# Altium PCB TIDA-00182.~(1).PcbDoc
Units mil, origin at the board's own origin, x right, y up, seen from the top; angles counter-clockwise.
Board outline 4330.71 x 3543.31 mil, 2 copper layers (Top Layer, Bottom Layer), stack 62 mil thick; 101 components, 43 nets, 202 pads, 57 vias.
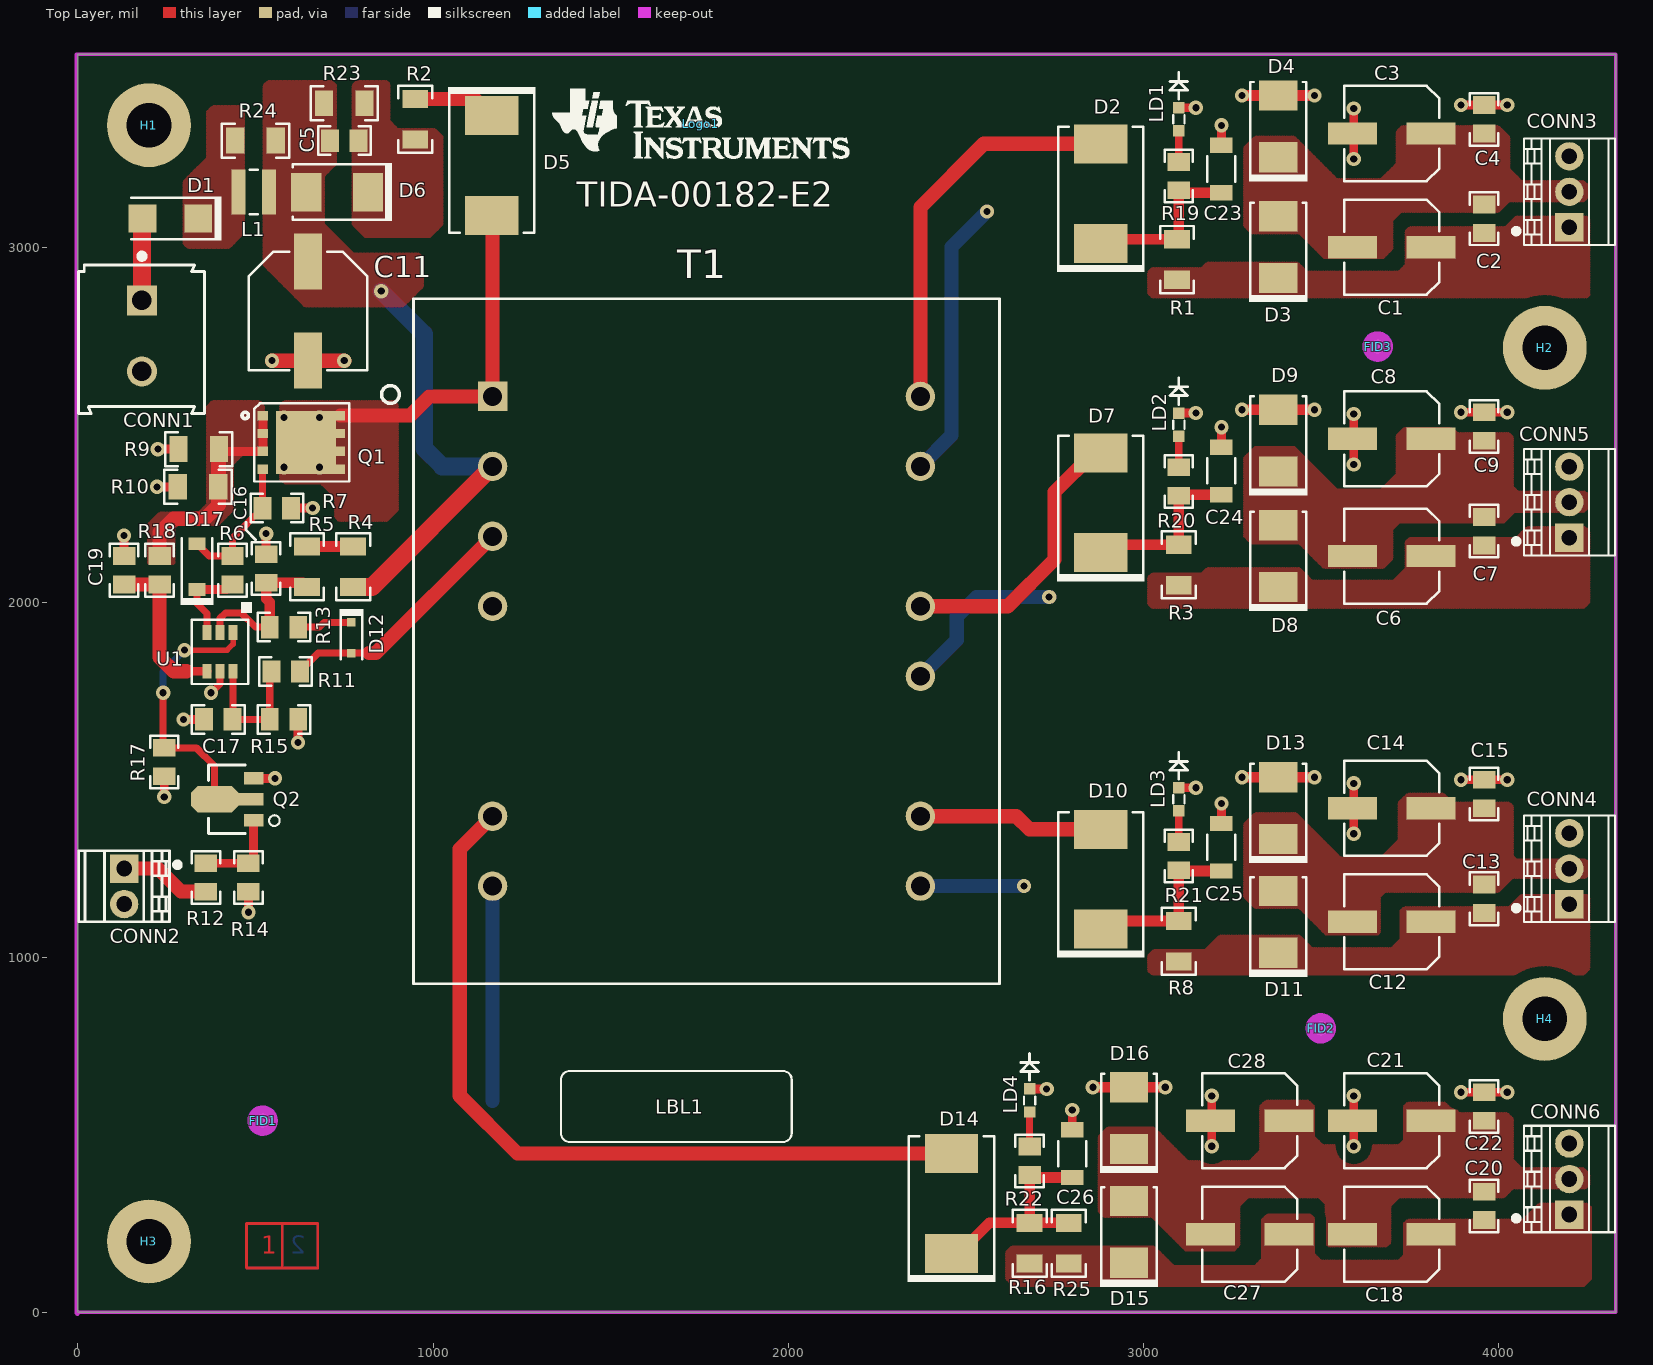
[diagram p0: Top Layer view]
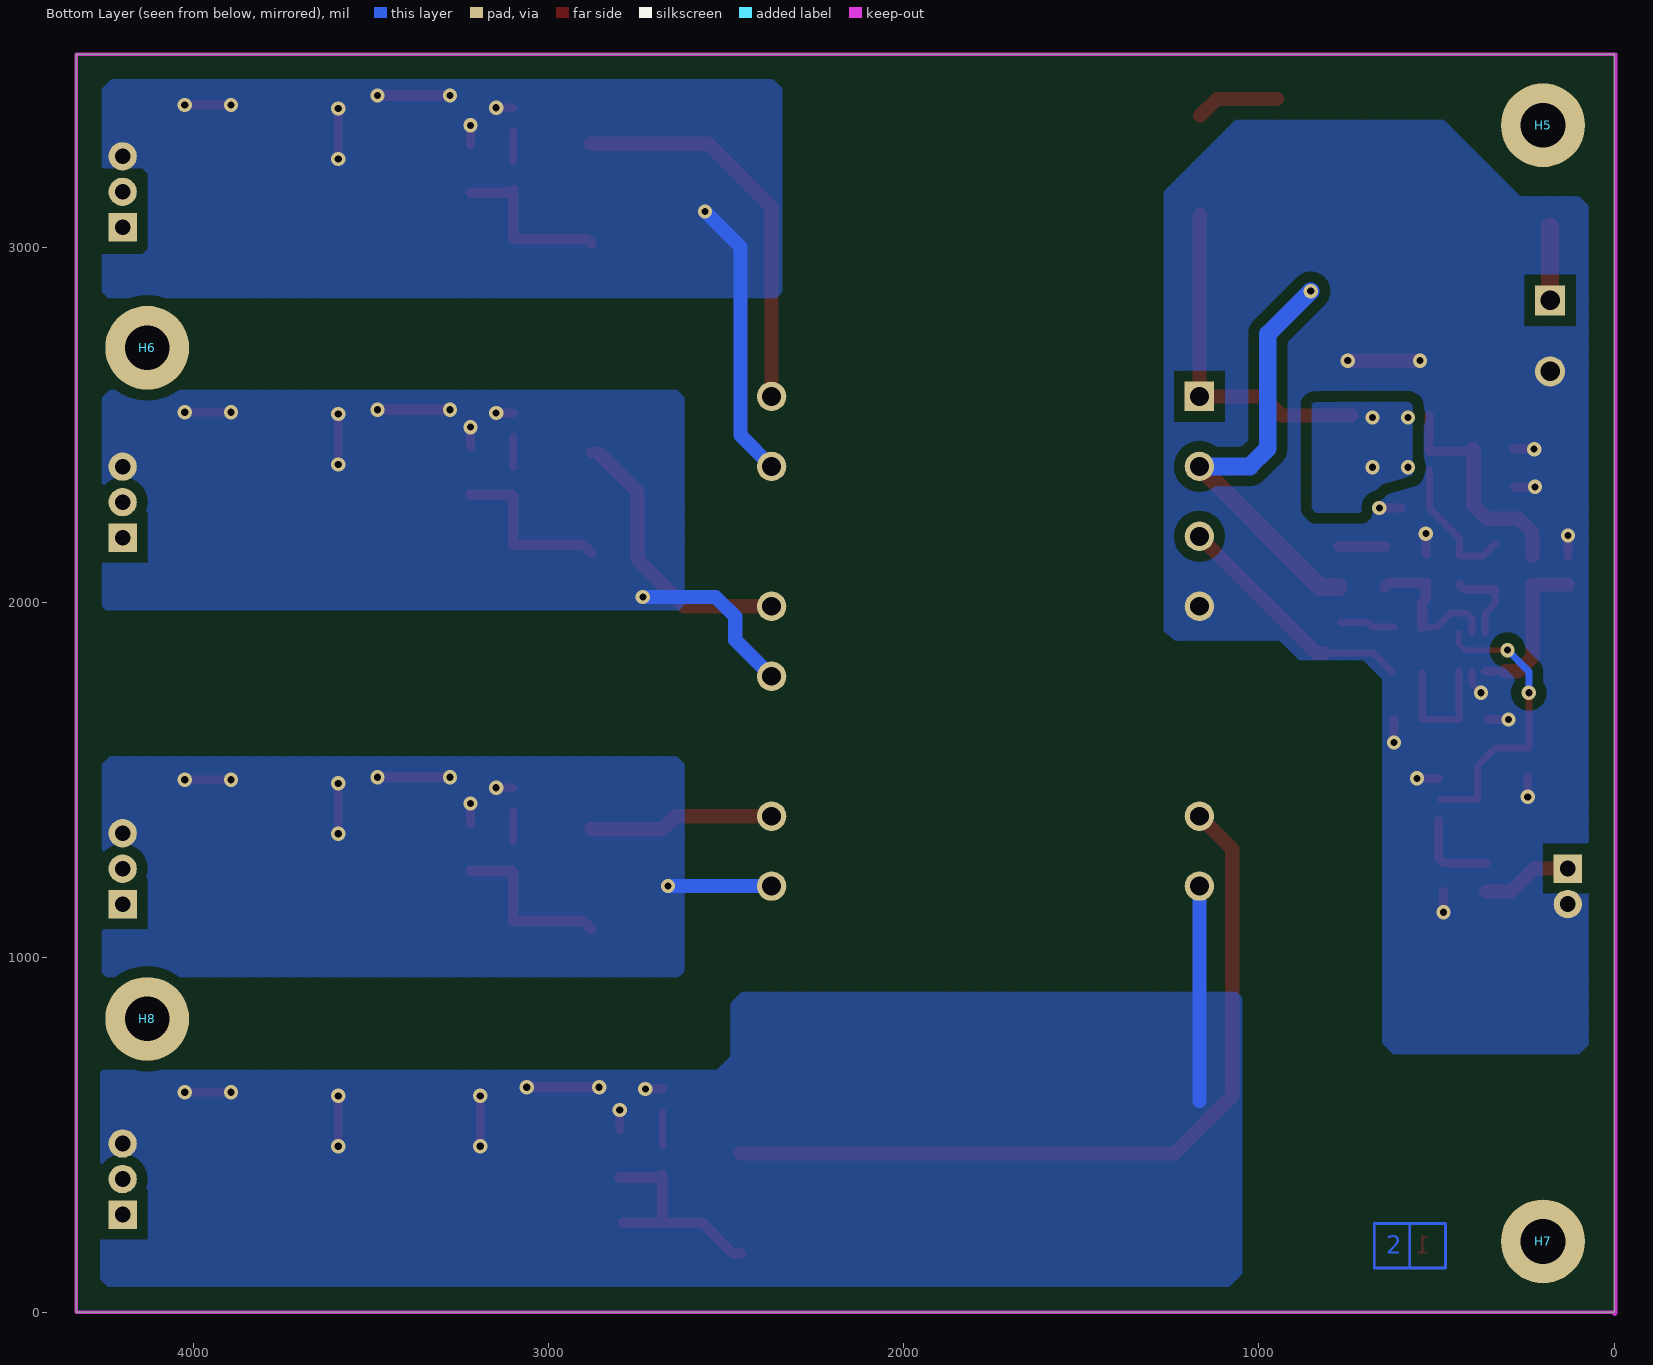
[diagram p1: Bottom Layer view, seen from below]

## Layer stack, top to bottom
Top Layer: signal copper 1.4
Dielectric: core 59.2, FR-4, Dk 4.8
Bottom Layer: signal copper 1.4

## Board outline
0,0 0,3543.31 4330.71,3543.31 4330.71,0

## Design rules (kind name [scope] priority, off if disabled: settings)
AcuteAngle [All] p1: minimum=4.50000000000000E+0001 checktracksonly=FALSE
AssemblyTestPointUsage [All] p1: valid=2
Clearance "SMT Pin Via" [IsVia vs IsSMTPin] p1: gap=12
Clearance "Via to Via" [IsVia vs IsVia] p2: gap=12
Clearance Clearance_Poly [InPolygon] p3: gap=30
Clearance [All] p4: gap=12
ComponentClearance ComponentClearance_Shunt [InComponentClass('Header') vs InComponentClass('Shunt')] p1: gap=0 collisioncheckmode=3 verticalgap=0 showdistances=FALSE
ComponentClearance ComponentClearance_Logo [InComponentClass('Logo')] p2: gap=50 collisioncheckmode=3 verticalgap=10 showdistances=FALSE
ComponentClearance ComponentClearance_ScrewToNut [(HasFootprint('NY PMS 440 0025 PH')) vs (HasFootprint('Keystone_1902C'))] p3: gap=5 collisioncheckmode=3 verticalgap=10 showdistances=FALSE
ComponentClearance ComponentClearance_MountingHoles [InComponentClass('Mounting Holes')] p4: gap=250 collisioncheckmode=3 verticalgap=100000 showdistances=FALSE
ComponentClearance ComponentClearance_SmallPassives [HasFootprint('0201*') or HasFootprint('0402*') or HasFootprint('0508') or HasFootprint('0603*') or HasFootprint('0612') or HasFootprint('0805*') or HasFootprint('0815*') or HasFootprint('0830*') or HasFootprint('1206*') or HasFootprint('1210*') or HasFootprint('1808*') or HasFootprint('1812*') or HasFootprint('1825*') or HasFootprint('2010*') or HasFootprint('2220*') or HasFootprint('2225*') or HasFootprint('2512*') or HasFootprint('2728*') or HasFootprint('3518*') vs HasFootprint('0201*') or HasFootprint('0402*') or HasFootprint('0508') or HasFootprint('0603*') or HasFootprint('0612') or HasFootprint('0805*') or HasFootprint('0815*') or HasFootprint('0830*') or HasFootprint('1206*') or HasFootprint('1210*') or HasFootprint('1808*') or HasFootprint('1812*') or HasFootprint('1825*') or HasFootprint('2010*') or HasFootprint('2220*') or HasFootprint('2225*') or HasFootprint('2512*') or HasFootprint('2728*') or HasFootprint('3518*')] p5: gap=20 collisioncheckmode=3 verticalgap=10 showdistances=FALSE
ComponentClearance ComponentClearance_THtoSMT [IsThruComponent vs IsSMTComponent] p6: gap=100 collisioncheckmode=3 verticalgap=30 showdistances=FALSE
ComponentClearance ComponentClearance_THtoTH [IsThruComponent vs IsThruComponent] p7: gap=118.11 collisioncheckmode=3 verticalgap=30 showdistances=FALSE
ComponentClearance [All] p8: gap=40 collisioncheckmode=3 verticalgap=10 showdistances=FALSE
DiffPairsRouting [All] p1: maxlimit=100 minlimit=10 mostfreqgap=10 maxuncoupledlength=1000
FabricationTestPointUsage TestPointUsage [All] p1: valid=2 allowmultiple=FALSE
FabricationTestpoint Testpoint [All] p1: side=3 testpointundercomponent=TRUE minsize=40 maxsize=100 preferedsize=60 minholesize=0 maxholesize=40 preferedholesize=32 testpointgrid=1 allowsidetop=TRUE allowsidebottom=TRUE usegrid=TRUE gridtolerance=0.01
FanoutControl Fanout_LCC [IsLCC] p1: bgadir=Out bgaviamode=Centered fanoutstyle=Auto fanoutdirection=Alternating viagrid=1 // Fanout_LCC (Default Rule)
FanoutControl Fanout_BGA [IsBGA] p2: bgadir=Out bgaviamode=Centered fanoutstyle=Auto fanoutdirection=Alternating viagrid=1 // Fanout_BGA (Default Rule)
FanoutControl Fanout_Default [All] p4: bgadir=Out bgaviamode=Centered fanoutstyle=Auto fanoutdirection=Alternating viagrid=1 // Fanout_Default (Default Rule)
FanoutControl Fanout_Small [(CompPinCount < 5)] p5: bgadir=Out bgaviamode=Centered fanoutstyle=Auto fanoutdirection=OutThenIn viagrid=1 // Fanout_Small (Default Rule)
HoleSize [All] p1: absolutevalues=TRUE maxlimit=251 minlimit=8 maxpercent=80.000 minpercent=20.000
MinimumAnnularRing MinimumAnnularRing_ThermalPadVias [IsVia and InAnyComponent] p1: minimumring=5.91
MinimumAnnularRing [All] p2: minimumring=9
MinimumSolderMaskSliver MinimumSolderMaskSliver_Logo [InComponentClass('Logo') vs InComponentClass('Logo')] p1: minsoldermaskwidth=0.7
MinimumSolderMaskSliver [All] p2: minsoldermaskwidth=3.94
PlaneConnect [All] p1: planeconnectstyle=Relief reliefexpansion=10 reliefentries=4 reliefconductorwidth=10 reliefairgap=10
PolygonConnect [All] p1: connectstyle=Direct reliefconductorwidth=10 reliefentries=4 polygonreliefangle="90 Angle" airgapwidth=10
RoutingVias [All] p1: holewidth=20 width=40 viastyle="Through Hole" minholewidth=16 minwidth=30 maxholewidth=20 maxwidth=40
SMDToCorner [All] p1: distance=30000
SilkToSilkClearance [All] p1: silktosilkclearance=5
SilkscreenOverComponentPads [All] p1: minsilkscreentomaskgap=5
SolderMaskExpansion [All] p1: expansion=2.5
Width [All] p1: maxlimit=100 minlimit=15 preferedwidth=40 checkconnectedcopper=TRUE
14 further rules are at their usual default settings.

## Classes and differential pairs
component class TIDA-00182-Main: C1 C2 C3 C4 C5 C6 C7 C8 C9 C11 C12 C13 C14 C15 C16 C17 C18 C19 C20 C21 C22 C23 C24 C25 C26 C27 C28 CONN1 CONN2 CONN3 CONN4 CONN5 CONN6 D1 D2 D3 D4 D5 D6 D7 D8 D9 D10 D11 D12 D13 D14 D15 D16 D17 L1 LD1 LD2 LD3 LD4 Q1 Q2 R1 R2 R3 R4 R5 R6 R7 R8 R9 R10 R11 R12 R13 R14 R15 R16 R17 R18 R19 R20 R21 R22 R23 R24 R25 T1 U1
component class "Mounting Holes": H1 H2 H3 H4
component class Logo: Logo1
component class Hardware_ANSI-B: FID1 FID2 FID3 H1 H2 H3 H4 H5 H6 H7 H8 LBL1 Logo1 ZZ1 ZZ2 ZZ3 ZZ4
component class FiducialMark: FID1 FID2 FID3
component class AssemblyNote: ZZ1 ZZ2 ZZ3 ZZ4
component class Label: LBL1

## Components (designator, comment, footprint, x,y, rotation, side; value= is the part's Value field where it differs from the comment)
C1 "EEH-ZA1V680XP" SM_RADIAL_6.3BMM 3700,3000 r180 top
C2 "08055C104JAT2A" 0805_HV 3960,3080 r90 top
C3 "EEH-ZA1V680XP" SM_RADIAL_6.3BMM 3700,3320 r180 top
C4 "08055C104JAT2A" 0805_HV 3960,3360 r90 top
C5 "GRM219R72A392KA01D" 0805_HV 750,3300 r180 top
C6 "EEH-ZA1V680XP" SM_RADIAL_6.3BMM 3700,2130 r180 top
C7 "08055C104JAT2A" 0805_HV 3960,2200 r90 top
C8 "EEH-ZA1V680XP" SM_RADIAL_6.3BMM 3700,2460 r180 top
C9 "08055C104JAT2A" 0805_HV 3960,2495 r90 top
C11 "EEE-FK1V221P" SM_RADIAL_F 648,2820 r270 top
C12 "EEH-ZA1V680XP" SM_RADIAL_6.3BMM 3700,1100 r180 top
C13 "08055C104JAT2A" 0805_HV 3960,1165 r90 top
C14 "EEH-ZA1V680XP" SM_RADIAL_6.3BMM 3700,1420 r180 top
C15 "08055C104JAT2A" 0805_HV 3960,1460 r90 top
C16 "C2012X5R1H225K125AB" 0805_HV 530,2095 r90 top
C17 "08053D334KAT2A" 0805_HV 395,1670 r180 top
C18 "EEH-ZA1V680XP" SM_RADIAL_6.3BMM 3700,220 r180 top
C19 "C2012X7R1H102K" 0805_HV 130,2090 r90 top
C20 "08055C104JAT2A" 0805_HV 3960,300 r90 top
C21 "EEH-ZA1V680XP" SM_RADIAL_6.3BMM 3700,540 r180 top
C22 "08055C104JAT2A" 0805_HV 3960,580 r90 top
C23 "10uF/50V" 1206_190 3220,3220 r90 top
C24 "10uF/50V" 1206_190 3220,2370 r90 top
C25 "10uF/50V" 1206_190 3220,1310 r90 top
C26 "10uF/50V" 1206_190 2800,447 r90 top
C27 "EEH-ZA1V680XP" SM_RADIAL_6.3BMM 3300,220 r180 top
C28 "EEH-ZA1V680XP" SM_RADIAL_6.3BMM 3300,540 r180 top
CONN1 "282841-2" TEC_282841-2 180,2750 r270 top
CONN2 "CON-OSTVN02A150" CN2_MTB_P100_PD80_D1.1_S5.54X6.5_STACK 130,1200 r270 top
CONN3 "CON-OSTVN03A150" TB_OSTVN03A150_3P 4200,3055.59 r90 top
CONN4 "CON-OSTVN03A150" TB_OSTVN03A150_3P 4200,1149.29 r90 top
CONN5 "CON-OSTVN03A150" TB_OSTVN03A150_3P 4200,2181.89 r90 top
CONN6 "CON-OSTVN03A150" TB_OSTVN03A150_3P 4200,275.59 r90 top
D1 "B260A-13-F" SMA 260,3080 r180 top
D2 "VS-30BQ100TRPBF" SMC 2880,3150.51 r90 top
D3 "3SMBJ5930B-TP" SMB 3380,3000.01 r90 top
D4 "3SMBJ5923B-TP" SMB 3380,3340.01 r90 top
D5 "SK510L-TP" SMC 1165,3230 r270 top
D6 "1SMB5937BT3G" SMB 730,3155 r180 top
D7 "VS-30BQ100TRPBF" SMC 2880,2280 r90 top
D8 "3SMBJ5930B-TP" SMB 3380,2130 r90 top
D9 "3SMBJ5923B-TP" SMB 3380,2455 r90 top
D10 "VS-30BQ100TRPBF" SMC 2880,1219.99 r90 top
D11 "3SMBJ5930B-TP" SMB 3380,1100.01 r90 top
D12 "BAS316,115" sod-323 770,1900 r270 top
D13 "3SMBJ5923B-TP" SMB 3380,1420 r90 top
D14 "VS-30BQ100TRPBF" SMC 2460,307 r90 top
D15 "3SMBJ5930B-TP" SMB 2960,227.01 r90 top
D16 "3SMBJ5923B-TP" SMB 2960,547 r90 top
D17 "MBR0520LT1G" SOD-123 335,2100 r90 top
FID1 "Fiducial" Fiducial10-20 520,540 r0 top
FID2 "Fiducial" Fiducial10-20 3500,800 r0 top
FID3 "Fiducial" Fiducial10-20 3660,2720 r0 top
H1 "NY PMS 440 0025 PH" "NY PMS 440 0025 PH" 200,3343.31 r0 top
H2 "NY PMS 440 0025 PH" "NY PMS 440 0025 PH" 4130.71,2716.54 r0 top locked
H3 "NY PMS 440 0025 PH" "NY PMS 440 0025 PH" 200,200 r0 top locked
H4 "NY PMS 440 0025 PH" "NY PMS 440 0025 PH" 4130.71,826.77 r0 top locked
H5 "1902C" Keystone_1902C 200,3343.31 r180 bottom
H6 "1902C" Keystone_1902C 4130.71,2716.54 r180 bottom locked
H7 "1902C" Keystone_1902C 200,200 r180 bottom locked
H8 "1902C" Keystone_1902C 4130.71,826.77 r180 bottom
L1 "744028220" WE-TPC_2811 495,3155 r0 top
LBL1 "Size: 0.65\" x 0.20 \"" Label_650x200 1685,580 r0 top
LD1 "LED_LG L29K-G2J1-24-Z" LED0603AA 3100,3360 r270 top
LD2 "LED_LG L29K-G2J1-24-Z" LED0603AA 3100,2500 r270 top
LD3 "LED_LG L29K-G2J1-24-Z" LED0603AA 3100,1445 r270 top
LD4 "LED_LG L29K-G2J1-24-Z" LED0603AA 2680,597 r270 top
Logo1 "Texas Instruments" TI_Stacked_SolderMask_Small 1754.09,3347.35 r0 top
Q1 "CSD19533Q5A" TRANS_NexFET_Q5A 630,2450 r0 top
Q2 "2DD1664R-13" SOT-89-3 420,1445 r180 top
R1 "RC1206FR-0712RL" 1206 3095,2965 r270 top
R2 "CRCW12061K00FKEA" 1206 950,3360 r90 top
R3 "RC1206FR-0712RL" 1206 3100,2105 r270 top
R4 "RC1206JR-070RL" 1206 775,2100 r270 top
R5 "ERJ-8ENF1002V" 1206 645,2100 r90 top
R6 "CRCW08055R10JNEA" 0805_HV 435,2090 r270 top
R7 "RG2012P-103-B-T5" 0805_HV 560,2265 r180 top
R8 "RC1206FR-0712RL" 1206 3100,1045 r270 top
R9 "CSR1206FKR200" 1206 340,2431 r0 top
R10 "CSR1206FKR200" 1206 338,2325 r0 top
R11 "RT0805BRD0744K8L" 0805_HV 585,1805 r0 top
R12 "CRCW08051K00FKEA" 0805_HV 360,1225 r270 top
R13 "CRCW0805100RFKEA" 0805_HV 580,1930 r0 top
R14 "RG2012P-103-B-T5" 0805_HV 480,1225 r90 top
R15 "CRCW080521K0FKEA" 0805_HV 580,1670 r180 top
R16 "CRCW12068R06FKEA" 1206 2680,195 r270 top
R17 "RG2012P-153-B-T5" 0805_HV 243,1550 r90 top
R18 "RR1220P-162-D" 0805_HV 230,2090 r270 top
R19 "CRCW080510K0JNEA" 0805_HV 3100,3200 r90 top
R20 "CRCW080510K0JNEA" 0805_HV 3100,2340 r90 top
R21 "CRCW080510K0JNEA" 0805_HV 3100,1285 r90 top
R22 "CRCW080510K0JNEA" 0805_HV 2680,427 r90 top
R23 "RC1206FR-071KL" 1206 750,3405 r0 top
R24 "RC1206JR-070RL" 1206 500,3300 r180 top
R25 "CRCW12068R06FKEA" 1206 2790,195 r270 top
T1 "ETD39/750342424" XFORMER_ETD39 1770,1890 r0 top
U1 "UCC28701DBVT" DBV-6 400,1860 r270 top
ZZ1 "This Assembly Note is for PCB labels only" AssemblyNoteLabel 188,4426 r0 top
ZZ2 "These assemblies are ESD sensitive, ESD precautions shall be observed." AssemblyNote 180,4347 r0 top
ZZ3 "These assemblies must be clean and free from flux and all contaminants. Use of no clean flux is not acceptable." AssemblyNote 175,4275 r0 top
ZZ4 "These assemblies must comply with workmanship standards IPC-A-610 Class 2, unless otherwise specified." AssemblyNote 173,4203 r0 top

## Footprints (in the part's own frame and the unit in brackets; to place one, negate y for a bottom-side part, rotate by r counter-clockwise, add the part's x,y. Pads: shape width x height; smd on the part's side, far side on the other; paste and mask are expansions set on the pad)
0805_HV [mil] "0805 with 30mil clearance between pads"
  rect 50x63 smd: 1(-40,0) 2(40,0)
  silkscreen extent -74,-40 74,40, body extent -43,-29 43,29, height 43
1206 [mm] "1206 from SM-752 data"
  rect 1.3x1.85 smd: 1(-1.45,0) 2(1.45,0)
  silkscreen extent -2.4,-1.21 2.4,1.21, body extent -1.7,-0.9 1.7,0.9, height 1.35
1206_190 [mm] "1206_190"
  rect 1.1x1.6 smd: 1(-1.7,0) 2(1.7,0)
  silkscreen extent -0.9,-1 0.9,1, body extent -1.75,-0.95 1.75,0.95, height 1.9
AssemblyNote [mil] "Assembly Note"
AssemblyNoteLabel [mil] "Assembly Note for PCB Labels"
CN2_MTB_P100_PD80_D1.1_S5.54X6.5_STACK [mil]
  rect 80x80 / inner round 80 / far side rect 80x80 hole 44: 1(-50,0)
  round 80 hole 44: 2(50,0)
  silkscreen extent -100,-128 100,160
DBV-6 [mil]
  rect 42x25 smd: 1(-54.5,37) 2(-54.5,0) 3(-54.5,-37) 4(54.5,-37) 5(54.5,0) 6(54.5,37)
  silkscreen extent -140,60 -110,90
Fiducial10-20 [mm]
  round 1 smd mask+0.5: 1(0,0)
  Top Layer keep-out circle w1.178: c0,0 r0.5
Keystone_1902C [mil] "Hex Standoff, 4-40 threaded, nylon"
  body extent -145,-126 146,126, height 501
Label_650x200 [mil] "Thermal Transfer Label"
  silkscreen extent -325,-100 325,100, body extent -326,-101 326,101, height 1
LED0603AA [mil]
  rect 32x32 smd: 1(-32.48,0) 2(32.48,0)
  silkscreen extent -132,-25 11,25
"NY PMS 440 0025 PH" [mm] "4-40 nylon screw and mounting hole"
  round 6 hole 3.2: 1(0,0)
  body extent -3.3,-3.3 3.3,3.3, height 2.69
SM_RADIAL_6.3BMM [mm] "Nichicon 6.3x7.7"
  rect 3.5x1.6 smd: 1(-2.8,0) 2(2.8,0)
  silkscreen extent -3.4,-3.4 3.4,3.4, body extent -3.41,-3.41 3.41,3.41, height 8
SM_RADIAL_F [mm] "8 x 10.2mm:  Panasonic F"
  rect 4x2 smd: 1(-3.55,0) 2(3.55,0)
  silkscreen extent -4.25,-4.25 4.25,4.25, body extent -4.26,-4.26 4.26,4.26, height 10.5
SMA [mm] "Molded Diode, 2-Leads, Body 4.3x2.6mm, IPC Medium Density, based on OnSemi component dimensions and land pattern"
  rect 2x2 smd: 1(-2,0) 2(2,0)
  silkscreen extent -3.66,-1.57 2.79,1.57, body extent -2.6,-1.3 2.6,1.3, height 2.42
SMB [mil] "Molded Diode, 2-Leads, Body 5.4x3.6mm, IPC Medium Density, based on OnSemi component dimensions"
  rect 85x107.99 smd: 1(-87.01,0) 2(87.01,0)
  silkscreen extent -155,-82 125,82, body extent -106,-71 106,71, height 91
SMC [mil] "Molded Diode, 2-Leads, Body 6.9x5.8mm, IPC Medium Density, based on OnSemi component dimensions and land patterns"
  rect 110x150 smd: 1(-140.49,0) 2(140.49,0)
  silkscreen extent -221,-123 189,124, body extent -156,-116 156,116, height 91
SOD-123 [mm] "On Semi recommended land pattern"
  rect 0.915x1.22 smd: 1(-1.637,0) 2(1.637,0)
  silkscreen extent -2.74,-1.17 2.03,1.17, body extent -1.93,-0.9 1.93,0.9, height 1.35
sod-323 [mm] "NXP recommended land pattern"
  rect 0.6x0.6 smd paste-0.05: 1(-1.1,0) 2(1.1,0)
  silkscreen extent -2.06,-0.86 1.53,0.86, body extent -1.3,-0.67 1.3,0.68, height 1.1
SOT-89-3 [mm] "SOT, 3-Leads, Body 4.6 x 2.6 mm, Pitch 1.5mm"
  rect 1.4x0.9 smd: 1(-1.9,1.5) 3(-1.9,-1.5)
  rect 1.8x0.9 smd: 2(-1.7,0)
  oct 3.4x1.9 smd: 4(0.9,0)
  silkscreen extent -1.3,-2.45 1.33,2.45, body extent -2.42,-2.28 1.83,2.32, height 1.62
TB_OSTVN03A150_3P [mil]
  rect 80x80 / inner round 80 / far side rect 80x80 hole 44: 1(0,0)
  round 80 hole 44: 2(100,0) 3(200,0)
  silkscreen extent -50,-128 250,160
TEC_282841-2 [mm] "TE Connectivity"
  rect 2.15x2.15 hole 1.4: 1(-2.54,0)
  round 2.15 hole 1.4: 2(2.54,0)
  silkscreen extent -5.9,-4.52 5.55,4.47, body extent -5.08,-4.52 5.58,4.48, height 15.2
TI_Stacked_SolderMask_Small [mil]
  silkscreen extent -418,-98 418,98
TRANS_NexFET_Q5A [mm] "TI recommended land pattern (nominal) M0139-01"
  rect 0.75x0.675 smd paste-0.1: 1(-2.776,1.917) 2(-2.776,0.639) 3(-2.776,-0.639) 4(-2.776,-1.917)
  rect 0.655x0.675 smd paste-0.1 mask+0.051: 5(2.776,-1.917) 6(2.776,-0.639) 7(2.776,0.639) 8(2.776,1.917)
  rect 4.295x4.51 smd paste-2.2: 9(0.301,0)
  silkscreen extent -3.4,-2.8 3.4,2.8, body extent -3.05,-2.5 3.05,2.5, height 1.11
WE-TPC_2811 [mm] "WURTH"
  rect 1x3.2 smd: 1(-1.1,0) 2(1.1,0)
  silkscreen extent -0.3,-1.6 0.3,1.6, body extent -1.5,-1.5 1.5,1.5, height 1.2
XFORMER_ETD39 [mil]
  rect 83x83 hole 53: 1(-602.5,689.5)
  round 83 hole 53: 2(-602.5,492.5) 3(-602.5,295.5) 4(-602.5,98.5) 7(-602.5,-492.5) 8(-602.5,-689.5) 9(602.5,-689.5) 10(602.5,-492.5) 12(602.5,-98.5) 13(602.5,98.5) 15(602.5,492.5) 16(602.5,689.5)
  silkscreen extent -915,-964 825,964, body extent -825,-964 825,964, height 1299

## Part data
C1 C3 C6 C8 C12 C14 C18 C21 C27 C28: library part UUD1V680MCL1GS, "CAP ALUM 68UF 35V 20% SMD"
C2 C4 C7 C9 C13 C15 C20 C22: "CAP, CERM, 0.1uF, 50V, +/-5%, X7R, 0805"
C5: "CAP, CERM, 3900pF, 100V, +/-10%, X7R, 0805"
C11: "CAP, AL, 220uF, 35V, +/-20%, 0.16 ohm, SMD"
C16: "CAP, CERM, 2.2uF, 50V, +/-10%, X5R, 0805"
C17: "CAP, CERM, 0.33uF, 25V, +/-10%, X5R, 0805"
C19: "CAP, CERM, 1000pF, 50V, +/-10%, X7R, 0805"
C23 C24 C25 C26: library part CGA5L3X5R1H106K160AB, "CAP, CERM, 10uF, 50V, +/-10%, X5R, 1206_190"
CONN1: "Terminal Block, 2x1, 5.08mm, TH"
CONN2: "Terminal Block, 4x1, 2.54mm, TH"
CONN3 CONN4 CONN5 CONN6: "CONN TERM BLOCK 2.54MM 3POS PCB"
D1: "Diode, Schottky, 60V, 2A, SMA"
D2 D7 D10 D14: "Diode, Schottky, 100V, 3A, SMC"
D3 D8 D11 D15: library part 1SMB5930BT3G, "DIODE ZENER 16V 3W DO214AA"
D4 D9 D13 D16: library part 1SMB5930BT3G, "DIODE ZENER 8.2V 3W DO214AA"
D5: library part MBRS3100T3G, "DIODE SCHOTTKY 100V 5A DO214AB"
D6: "Diode, Zener, 33V, 550mW, SMB"
D12: "Diode, Ultrafast, 100V, 0.25A, SOD-323"
D17: "Diode, Schottky, 20V, 0.5A, SOD-123"
FID1 FID2 FID3: "Fiducial mark.  There is nothing to buy or mount."
H1 H2 H3 H4: "Machine Screw, Round, #4-40 x 1/4, Nylon, Philips panhead"
H5 H6 H7 H8: "Standoff, Hex, 0.5\"L #4-40 Nylon"
L1: "Inductor, Shielded Drum Core, Ferrite, 22uH, 0.27A, 1.22 ohm, SMD"
LBL1: library part THT-14-423-10, "Thermal Transfer Printable Labels, 0.650\" W x 0.200\" H - 10,000 per roll"
LD1 LD2 LD3 LD4: "LED SmartLED Green 570NM"
Logo1: library part TI_Logo, "Texas Instrument Corporate Signature"
Q1: "MOSFET, N-CH, 100V, 13A, SON 5x6mm"
Q2: library part "2DD1664R-13, Diodes Inc.", "Transistor, NPN, 32V, 1A, SOT-89"
R1 R3 R8: "RES, 12.0 ohm, 1%, 0.25W, 1206"
R2: "RES, 1.00 ohm, 1%, 0.25W, 1206"
R4 R24: "RES, 0 ohm, 5%, 0.25W, 1206"
R5: "RES, 10.0k ohm, 1%, 0.25W, 1206"
R6: "RES, 5.1 ohm, 5%, 0.125W, 0805"
R7 R14: "RES, 10.0k ohm, 0.1%, 0.125W, 0805"
R9 R10: "RES, 0.2 ohm, 1%, 0.5W, 1206"
R11: "RES, 44.8k ohm, 0.1%, 0.125W, 0805"
R12: "RES, 1.00k ohm, 1%, 0.125W, 0805"
R13: "RES, 100 ohm, 1%, 0.125W, 0805"
R15: "RES, 21.0k ohm, 1%, 0.125W, 0805"
R16 R25: "RES, 8.06 ohm, 1%, 0.25W, 1206"
R17: "RES, 15.0k ohm, 0.1%, 0.125W, 0805"
R18: "RES, 1.60k ohm, 0.5%, 0.1W, 0805"
R19 R20 R21 R22: "RES, 10k ohm, 5%, 0.125W, 0805"
R23: "RES, 1.00k ohm, 1%, 0.25W, 1206"
T1: library part ETD39/750342366, "Transformer,   TH"
U1: library part UCC28701DBV, "IC, Constant Voltage, Constant Current PWM With Primary Side Regulation"
ZZ1: library part AssemblyNoteLabel
ZZ2 ZZ3 ZZ4: library part AssemblyNote

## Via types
v1: diameter 40, hole 20, Top Layer to Bottom Layer, tented both sides, 52 vias
v2: diameter 40, hole 20, Top Layer to Bottom Layer, 5 vias

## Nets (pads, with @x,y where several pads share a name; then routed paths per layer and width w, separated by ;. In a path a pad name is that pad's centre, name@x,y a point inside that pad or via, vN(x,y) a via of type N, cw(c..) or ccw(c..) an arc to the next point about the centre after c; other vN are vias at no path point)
CS: Q1.1 Q1.2 Q1.3 R9.2 R10.2 R18.1 | length 801.4
  Top Layer w25: R9.2@395.09,2424.84 397.09,2424.84 Q1.3 Q1.2 Q1.1
  Top Layer w40: R18.1 230,2196 269.12,2235.12 358.12,2235.12 395.09,2272.09 ; R9.2@395.09,2424.84 R10.2 395.09,2272.09 ; R9.2 397.09,2424.84 397.09,2274.09 395.09,2272.09
DRV: D17.1 R6.2 U1.3 | length 238.6
  Top Layer w20: D17.1 335,1996 363,1968 U1.3
  Top Layer w25: D17.1 420.53,2035.53 R6.2
GND: C11.2 C16.2 C17.2 C19.2 CONN1.2 CONN2.2 Q2.3 R7.1 R9.1 R10.1 R14.1 R15.1 R17.1 T1.4 U1.5 | length 866.6
  Top Layer w20: v1(375,1745) 400,1770 U1.5
  Top Layer w25: C19.2 v1(130,2188) ; v1(222.91,2325) R10.1 ; v1(224.91,2431) R9.1 ; v1(243,1452) R17.1 ; v1(297,1670) C17.2 ; v1(480,1127) R14.1 ; Q2.3 v1(555,1504.06) ; C16.2 v2(530,2193) ; R7.1 v2(661,2265) ; v1(620,1605) R15.1
  Top Layer w40: v2(546.24,2680.24) C11.2 v2(749.76,2680.24)
GND1: C3.2 C4.2 C23.2 CONN3.3 D4.2 LD1.1 T1.15 | length 1375.2
  Top Layer w25: LD1.1 v1(3148,3392.48) ; C23.2 v1(3220,3343) ; v1(3592.73,3248.06) 3592.73,3319.03 v1(3592.73,3390) ; v1(3895,3400) C4.2 v1(4025,3400)
  Top Layer w30: v1(3278,3427.02) D4.2 v1(3482,3427.02)
  Bottom Layer w40: T1.15 2460,2470 2460,3000 v1(2560,3100)
GND2: C8.2 C9.2 C24.2 CONN5.3 D9.2 LD2.1 T1.12 | length 1073.7
  Top Layer w25: LD2.1 v1(3148,2532.48) ; C24.2 v1(3220,2493) ; v1(3592.73,2388.06) 3592.73,2459.03 v1(3592.73,2530) ; v1(3895,2535) C9.2 v1(4025,2535)
  Top Layer w30: v1(3278,2542.01) D9.2 v1(3482,2542.01)
  Bottom Layer w40: T1.12 2475,1894 2475,1960 2530,2015 v1(2735,2015)
GND3: C14.2 C15.2 C25.2 CONN4.3 D13.2 LD3.1 T1.9 | length 872
  Top Layer w25: LD3.1 v1(3148,1477.48) ; C25.2 v1(3220,1433) ; v1(3592.73,1348.06) 3592.73,1419.03 v1(3592.73,1490) ; v1(3895,1500) C15.2 v1(4025,1500)
  Top Layer w30: v1(3278,1507.01) D13.2 v1(3482,1507.01)
  Bottom Layer w40: T1.9 v1(2664.5,1200.5)
GND4: C21.2 C22.2 C26.2 C28.2 CONN6.3 D16.2 LD4.1 T1.8 | length 1326.5
  Top Layer w25: LD4.1 v1(2728,629.48) ; C26.2 v1(2800,570) ; v1(3192.73,468.06) v1(3192.73,610) ; v1(3592.73,468.06) v1(3592.73,610) ; v1(3895,620) C22.2 v1(4025,620)
  Top Layer w30: v1(2858,634.01) D16.2 v1(3062,634.01)
  Bottom Layer w40: 1167.5,596 T1.8
NetC5_1: C5.1 D6.1 R2.1 R23.2
NetC5_2: C5.2 C11.1 D6.2 L1.2 R4.2 R23.1 R24.1 T1.2 | length 1239.7
  Top Layer w50: R4.2 827.91,2042.91 T1.2
  Bottom Layer w50: v2(854,2876) 975,2755 975,2433 1025.5,2382.5 T1.2
NetC16_1: C16.1 R5.1 R13.1 U1.2 | length 452.4
  Top Layer w20: U1.2 400,1955 415,1970 460,1970 500,1930 R13.1
  Top Layer w30: R13.1 540,2000 530,2010 C16.1 632.91,2055 R5.1
NetC17_1: C17.1 R11.1 R15.2 U1.6 | length 371.3
  Top Layer w20: U1.6 437,1672 C17.1 R15.2 R11.1@540,1800
NetC19_1: C19.1 R18.2 U1.4 | length 454.4
  Top Layer w25: 305.5,1805.5 U1.4
  Top Layer w40: C19.1 R18.2 230,1845 269.5,1805.5 305.5,1805.5
NetC23_1: C23.1 D2.1 R1.1 R19.1 | length 480.8
  Top Layer w30: D2.1 2892.07,3022.09 R1.1 ; R1.1@3095,3027.09 3100,3027.09 R19.1 3106.93,3153.07 C23.1
NetC24_1: C24.1 D7.1 R3.1 R20.1 | length 488.7
  Top Layer w30: D7.1 2902.58,2162.09 R3.1@3099.51,2162.09 ; R3.1 R3.1@3099.51,2162.09 ; C24.1 3103.07,2303.07 R20.1 3099.51,2299.51 R3.1@3099.51,2162.09
NetC25_1: C25.1 D10.1 R8.1 R21.1 | length 479.2
  Top Layer w30: D10.1 2902.59,1102.09 R8.1 ; R21.1@3099.51,1239.51 R21.1@3100,1240 ; R8.1@3100,1112.09 R21.1@3100,1240 ; C25.1 3103.07,1243.07 R21.1@3100,1240
NetC26_1: C26.1 D14.1 R16.1 R22.1 R25.1 | length 611.2
  Top Layer w30: D14.1 2481.51,166.51 2567.09,252.09 R16.1 R25.1 ; R16.1@2680,264.09 R22.1 2686.93,380.07 C26.1
NetCONN1_1: CONN1.1 D1.2 | length 208.7
  Top Layer w50: CONN1.1 D1.2@180,3058.74
NetCONN2_1: CONN2.1 R12.2 | length 256.9
  Top Layer w40: CONN2.1 225,1250 290,1185 R12.2
NetD1_1: D1.1 L1.1 R24.2
NetD2_2: D2.2 T1.16 | length 1114.4
  Top Layer w40: T1.16 2372.5,3112.5 2551,3291 D2.2
NetD5_1: D5.1 R2.2 | length 234.3
  Top Layer w40: R2.2 1118.41,3417.09 D5.1
NetD5_2: D5.2 Q1.5 Q1.6 Q1.7 Q1.8 Q1.9 T1.1 | length 961.6
  Top Layer w40: Q1.8 935.49,2525.49 989.5,2579.5 T1.1 1167.5,3087.01 D5.2
  other v1: 580,2380 680,2380 580,2520 680,2520
NetD7_2: D7.2 T1.13 | length 797.7
  Top Layer w30: D7.2@2860.49,2420.49 D7.2
  Top Layer w40: T1.13 2618.5,1988.5 2750,2120 2750,2310 D7.2@2860.49,2420.49
NetD10_2: D10.2 T1.10 | length 522.8
  Top Layer w40: T1.10 2642.5,1397.5 2679.52,1360.48 D10.2
NetD12_1: D12.1 R13.2 | length 155.5
  Top Layer w20: R13.2 680,1930 693.31,1943.31 D12.1
NetD12_2: D12.2 R11.2 T1.3 | length 700.1
  Top Layer w20: R11.2 676.69,1856.69 D12.2 820,1856.69
  Top Layer w40: 820,1856.69 838.69,1856.69 T1.3
NetD14_2: D14.2 T1.7 | length 2278.1
  Top Layer w40: T1.7 1075,1305 1075,610 1237.51,447.49 D14.2
NetD17_2: D17.2 Q1.4 R6.1 R7.2 | length 393.3
  Top Layer w20: D17.2 369.47,2130 R6.1 435,2180 R7.2 Q1.4@520,2373.81
NetLD1_2: LD1.2 R19.2 | length 87.5
  Top Layer w20: R19.2 LD1.2
NetLD2_2: LD2.2 R20.2 | length 87.5
  Top Layer w20: R20.2 LD2.2
NetLD3_2: LD3.2 R21.2 | length 87.5
  Top Layer w20: R21.2 LD3.2
NetLD4_2: LD4.2 R22.2 | length 97.5
  Top Layer w20: R22.2 LD4.2
NetQ2_1: Q2.1 R12.1 R14.2 | length 247.1
  Top Layer w25: R12.1 R14.2 494.8,1279.8 Q2.1
NetR4_1: R4.1 R5.2 | length 130
  Top Layer w30: R5.2 R4.1
REF_B: C18.2 C20.2 C21.1 C22.1 C27.2 C28.1 CONN6.2 D15.2 D16.1
REF_U_T: C1.2 C2.2 C3.1 C4.1 CONN3.2 D3.2 D4.1
REF_V_T: C6.2 C7.2 C8.1 C9.1 CONN5.2 D8.2 D9.1
REF_W_T: C12.2 C13.2 C14.1 C15.1 CONN4.2 D11.2 D13.1
SD: Q2.2 Q2.4 R17.2 U1.1 | length 838.1
  Top Layer w15: v1(300,1865) 420,1865 437,1882 U1.1
  Top Layer w20: v1(240,1745) 240,1590 R17.2 333,1590 384.57,1538.43 Q2.4 Q2.2
  Bottom Layer w20: v1(240,1745) 240,1805 v1(300,1865)
VCC_B: C18.1 C20.1 C27.1 CONN6.1 D15.1 R16.2 R25.2
VCC_U_T: C1.1 C2.1 CONN3.1 D3.1 R1.2
VCC_V_T: C6.1 C7.1 CONN5.1 D8.1 R3.2
VCC_W_T: C12.1 C13.1 CONN4.1 D11.1 R8.2
pads on no net: FID1.1 FID2.1 FID3.1 H1.1 H2.1 H3.1 H4.1
copper on no net: | length 1550
  Top Layer w7.87: 575,125 575,250 ; 475,125 475,250 675,250 675,125 475,125
  Bottom Layer w7.87: 575,125 575,250 ; 475,125 675,125 675,250 475,250 475,125

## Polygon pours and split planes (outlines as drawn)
REF_B on Top Layer "Top Layer-No Net" (hatched 90Degree grid 5 track 8, remove dead copper, pour order 34): 3685,187 3522,187 3515,194 3515,305 3495,325 3295,325 3270,300 3270,190 3255,175 3120,175 3025,270 2890,270 2875,285 2875,495 2900,520 3030,520 3125,425 3300,425 3330,455 3330,580 3345,595 3465,595 3480,580 3480,495 3505,470 3720,470 3735,485 3735,580 3745,590 3860,590 3890,560 4025,560 4040,545 4040,430 4065,405 4240,405 4255,390 4255,360 4245,350 4040,350 4015,325 3720,325 3695,300 3695,197
REF_V_T on Top Layer "Top Layer-No Net" (hatched 90Degree grid 5 track 8, remove dead copper, pour order 30): 3510,2096.3 3440,2166.3 3305,2166.3 3285,2186.3 3285,2406.3 3315,2436.3 3425,2436.3 3545,2316.3 3670,2316.3 3715,2361.3 3715,2470 3735,2490 3870,2490 3885,2475 4030,2475 4040,2465 4040,2325 4055,2310 4245,2310 4250,2305 4250,2265 4240,2255 4045,2255 4015,2225 3720,2225 3700,2205 3700,2121.3 3675,2096.3
VCC_B on Top Layer "Top Layer-No Net" (hatched 90Degree grid 5 track 8, remove dead copper, pour order 33): 2630,185 3030,185 3085,130 3315,130 3335,150 3335,260 3350,275 3470,275 3480,265 3480,165 3500,145 3720,145 3735,160 3735,250 3745,260 4070,260 4115,305 4250,305 4260,295 4260,95 4240,75 2635,75 2615,95 2615,170
VCC_U_T on Top Layer "Top Layer-No Net" (hatched 90Degree grid 5 track 8, remove dead copper, pour order 27): 4250,3085 4255,3080 4255,2865 4250,2860 3025,2860 3015,2870 3015,2930 3025,2940 3165,2940 3180,2955 3435,2955 3460,2930 3720,2930 3740,2950 3740,3045 3750,3055 4020,3055 4050,3085
REF_U_T on Top Layer "Top Layer-No Net" (hatched 90Degree grid 5 track 8, remove dead copper, pour order 31): 3510,2970 3440,3040 3305,3040 3285,3060 3285,3280 3315,3310 3425,3310 3545,3190 3670,3190 3715,3235 3715,3325 3730,3340 4000,3340 4030,3310 4030,3220 4065,3185 4240,3185 4250,3175 4250,3140 4240,3130 4030,3130 4000,3100 3725,3100 3700,3075 3700,2995 3675,2970
VCC_V_T on Top Layer "Top Layer-No Net" (hatched 90Degree grid 5 track 8, remove dead copper, pour order 26): 4245,2210 4255,2200 4255,2000 4240,1985 3025,1985 3015,1995 3015,2070 3025,2080 3165,2080 3180,2095 3440,2095 3475,2060 3705,2060 3740,2095 3740,2170 3750,2180 4050,2180 4080,2210
VCC_W_T on Top Layer "Top Layer-No Net" (hatched 90Degree grid 5 track 8, remove dead copper, pour order 24): 4250,1175 4255,1170 4255,967.4 4240,952.4 3025,952.4 3015,962.4 3015,1005 3030,1020 3175,1020 3215,1060 3440,1060 3475,1025 3700,1025 3725,1050 3725,1130 3735,1140 4030,1140 4065,1175
REF_W_T on Top Layer "Top Layer-No Net" (hatched 90Degree grid 5 track 8, remove dead copper, pour order 29): 3515,1065 3440,1140 3315,1140 3285,1170 3285,1375 3315,1405 3430,1405 3555,1280 3670,1280 3720,1330 3720,1435 3745,1460 3845,1460 3870,1435 4030,1435 4040,1425 4040,1285 4050,1275 4245,1275 4250,1270 4250,1230 4245,1225 4040,1225 4000,1185 3680,1185 3665,1170 3665,1070 3660,1065
NetC5_1 on Top Layer "Top Layer-No Net 1" (hatched 90Degree grid 5 track 10, remove dead copper, pour order 23): 775,3455 775,3065 810,3030 960,3030 990,3030 1020,3060 1025,3065 1025,3245 1025,3310 1010,3325 1005,3330 900,3330 875,3355 875,3375 875,3460 870,3465 825,3465 785,3465 775,3455
NetD1_1 on Top Layer "Top Layer-No Net 1" (hatched 90Degree grid 5 track 10, remove dead copper, pour order 28): 425,3000 465,3040 465,3385 455,3395 380,3395 365,3380 365,3250 300,3185 300,3010 310,3000
NetC5_2 on Top Layer "Top Layer-No Net 1" (hatched 90Degree grid 5 track 10, remove dead copper, pour order 25): 525,2950 525,3455 535,3465 715,3465 725,3455 725,3235 690,3200 690,3065 775,2980 960,2980 970,2970 970,2890 915,2835 640,2835
NetD5_2 on Top Layer "Top Layer-No Net" (hatched 90Degree grid 5 track 8, remove dead copper, pour order 22): 725,2240 735,2230 870,2230 900,2260 900,2555 890,2565 580,2565 570,2555 570,2345 585,2335 685,2335 725,2295
CS on Top Layer "Top Layer-No Net 1" (hatched 90Degree grid 5 track 10, remove dead copper, pour order 20): 525,2420 525,2550 510,2565 380,2565 365,2550 365,2275 340,2250 230,2250 200,2220 200,2105 270,2105 270,2210 280,2220 395,2220 435,2260 435,2390 465,2420
GND on Bottom Layer "Top Layer-No Net" (hatched 90Degree grid 5 track 8, remove dead copper, pour order 38): 620,730 100,730 75,755 75,3115 100,3140 265,3140 480,3355 1065,3355 1265,3155 1265,1920 1235,1895 940,1895 885,1840 705,1840 650,1785 650,760
GND4 on Bottom Layer "Top Layer-No Net" (hatched 90Degree grid 5 track 8, remove dead copper, pour order 37): 4255,680 2525,680 2485,720 2485,870 2455,900 1065,900 1050,885 1050,110 1085,75 4240,75 4260,95 4260,675
GND3 on Bottom Layer "Top Layer-No Net" (hatched 90Degree grid 5 track 8, remove dead copper, pour order 35): 2635,947.4 2990,947.4 4245,947.4 4255,957.4 4255,1023.4 4255,1542.4 4240,1557.4 4235,1562.4 4190,1562.4 2640,1562.4 2620,1542.4 2620,1417.4 2620,962.4 2635,947.4
GND1 on Bottom Layer "Top Layer-No Net" (hatched 90Degree grid 5 track 8, remove dead copper, pour order 32): 2360,2860 2345,2875 2345,3445 2370,3470 4230,3470 4255,3445 4255,2875 4240,2860
GND2 on Bottom Layer "Top Layer-No Net" (hatched 90Degree grid 5 track 8, remove dead copper, pour order 36): 2635,1980 2990,1980 4245,1980 4255,1990 4255,2056 4255,2575 4240,2590 4235,2595 4190,2595 2640,2595 2620,2575 2620,2450 2620,1995 2635,1980
NetD5_2 on Bottom Layer "Top Layer-No Net" (hatched 90Degree grid 5 track 8, remove dead copper, pour order 21): 710,2255 838,2255 848,2265 848,2556.67 843,2560 730,2561 580,2561 570,2555 570,2360 600,2351 655,2335 700,2290 700,2265

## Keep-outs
Keep-Out Layer:
  lines w10: -5,3543.31 -5,0 ; 0,0 4330.71,0 4330.71,3543.31 0,3543.31 ; -5,0 ccw(c0,0) 0,-5 ; -5,0 ccw(c0,0) 0,-5 ; -5,0 ccw(c0,0) 0,-5 ; -5,0 ccw(c0,0) 0,-5 ; -5,0 ccw(c0,0) 0,-5 ; -5,0 ccw(c0,0) 0,-5
  text ".Layer_Name" at 577,-858.49 h60

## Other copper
Top Layer:
  text "1" at 516,165 h50
  text ".Layer_Name" at 577,-858.49 h60
Bottom Layer:
  pour cut-out: 4255,2976 4143.59,2976 4126,2993.59 4126,3208 4144,3226 4267.4,3226 4267.4,2988.4
  text "2" at 642,165 h50
  text ".Layer_Name" at 577,-858.49 h60

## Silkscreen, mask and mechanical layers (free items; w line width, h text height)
Top Overlay:
  circle w10: c470.94,2526 r9.06
  circle w6: c553,1385 r15
  lines w6: 320.5,1769.5 479.5,1769.5 479.5,1950.5 320.5,1950.5 320.5,1769.5
  lines w7.87: 473,2225 473,2203 500,2176
  text "TIDA-00182-E2" at 1405,3090 h120
  text ".Layer_Name" at 577,-858.49 h60
Bottom Overlay:
  text ".Layer_Name" at 577,-858.49 h60
Top Paste:
  text ".Layer_Name" at 577,-858.49 h60
Bottom Paste:
  text ".Layer_Name" at 577,-858.49 h60
Top Solder:
  text ".Layer_Name" at 577,-858.49 h60
  text ".Layer_Name" at 577,-858.49 h60
Bottom Solder:
  text ".Layer_Name" at 577,-858.49 h60
Drill Guide:
  text ".Layer_Name" at 577,-858.49 h60
M1 Board Outline:
  the board outline again, w10
  text ".Layer_Name" at 576,-857 h60
M2 Board Dimensions:
  rectangle: -0.5,-285.5 124.5,-160.5
  rectangle: 124.5,-410.5 499.5,-285.5
  lines w6: 728.35,63.31 728.35,1820 1220,1820
  lines w7: -0.5,-285.5 999.5,-285.5 ; 124.5,-410.5 124.5,-160.5 ; 249.5,-410.5 249.5,-160.5 ; 499.5,-410.5 499.5,-160.5 ; 749.5,-410.5 749.5,-160.5 ; -0.5,-410.5 999.5,-410.5 999.5,-160.5 -0.5,-160.5 -0.5,-410.5
  lines w7.87: 0,63.31 4330.71,63.31 ; 0,3480 4330.71,3480 ; 63.31,0 63.31,3480 ; 2544.98,937.01 4330.71,937.01 ; 2544.98,2606.3 4330.71,2606.3 ; 2546.24,935.75 2546.24,700 4330.71,700 ; 2546.24,1573.7 4330.71,1573.7 ; 2546.24,1969.61 4330.71,1969.61 ; 2546.24,2843.31 4330.71,2843.31 ; 4267.4,0 4267.4,3480
  lines w10: -0.5,-475.5 -0.5,-455.5 ; 59.5,-485.5 -0.5,-465.5 ; 59.5,-445.5 -0.5,-465.5 ; 223.58,-465.5 -0.5,-465.5 ; 775.42,-465.5 999.5,-465.5 ; 939.5,-485.5 999.5,-465.5 ; 939.5,-445.5 999.5,-465.5 ; 999.5,-475.5 999.5,-455.5
  text "1000 (mil)" at 233.58,-501.49 h60
  text ".Layer_Name" at 577,-858.49 h60
M3 3D STEP Top:
  text ".Layer_Name" at 577,-858.49 h60
M4 3D STEP Bottom:
  text ".Layer_Name" at 577,-858.49 h60
M5 Assembly Top:
  lines w6: 2654.96,703.79 2704.96,703.79 ; 2664.25,585.58 2664.25,608.42 ; 2679.96,653.79 2679.96,678.79 ; 2679.96,728.79 2679.96,703.79 ; 2695.75,585.58 2695.75,608.42 ; 3074.96,1551.79 3124.96,1551.79 ; 3074.96,2606.79 3124.96,2606.79 ; 3074.96,3466.79 3124.96,3466.79 ; 3084.25,1433.58 3084.25,1456.42 ; 3084.25,2488.58 3084.25,2511.42 ; 3084.25,3348.58 3084.25,3371.42 ; 3099.96,1501.79 3099.96,1526.79 ; 3099.96,1576.79 3099.96,1551.79 ; 3099.96,2556.79 3099.96,2581.79 ; 3099.96,2631.79 3099.96,2606.79 ; 3099.96,3416.79 3099.96,3441.79 ; 3099.96,3491.79 3099.96,3466.79 ; 3115.75,1433.58 3115.75,1456.42 ; 3115.75,2488.58 3115.75,2511.42 ; 3115.75,3348.58 3115.75,3371.42 ; 2679.96,703.79 2654.96,678.79 2704.96,678.79 2679.96,703.79 ; 3099.96,1551.79 3124.96,1526.79 3074.96,1526.79 3099.96,1551.79 ; 3099.96,2606.79 3074.96,2581.79 3124.96,2581.79 3099.96,2606.79 ; 3099.96,3466.79 3074.96,3441.79 3124.96,3441.79 3099.96,3466.79
  lines w7.87: 19.76,1100 19.76,1300 ; 74.88,1100 74.88,1300 ; 185.12,1100 185.12,1300 ; 208.74,1100 208.74,1300 ; 208.74,1129.53 257.95,1129.53 ; 208.74,1170.47 257.95,1170.47 ; 208.74,1229.53 257.95,1229.53 ; 208.74,1270.47 257.95,1270.47 ; 228.43,1133.07 228.43,1168.5 ; 228.43,1231.5 228.43,1270.47 ; 236.3,1100 236.3,1129.13 ; 236.3,1172.44 236.3,1227.56 ; 236.3,1270.87 236.3,1300 ; 248.11,1133.07 248.11,1168.5 ; 248.11,1231.5 248.11,1270.47 ; 2.05,1100 2.05,1300 257.95,1300 257.95,1100 2.05,1100
  lines w10: -292,-930.17 6308,-930.17 ; -292,-726.83 6310,-726.83 ; -292,-523.5 -292,-1133.5 3713,-1133.5 6310,-1133.5 6310,-523.5 -291.5,-523.5 -291.5,-1133.5 1284,-1133.5 ; 2173,-1133.5 2173,-523.5 ; 3440,-726.83 3440,-523.5 ; 4280,-726.83 4280,-523.5 ; 4902,-1140 4902,-937.17
  text "LD1" at 3056,3349.99 h40 r90
  text "LD2" at 3065,2480 h40 r90
  text "LD3" at 3060,1420 h40 r90
  text "C0NN2" at 90,1040 h40
  text "LD4" at 2645,560 h40 r90
  text "COMPONENTS MARKED 'DNP' SHOULD NOT BE POPULATED." at 1153.5,-318.5 h60
  text "ASSEMBLY VARIANT:" at 1153,-434 h60
  text ".VariantName" at 2189,-434 h60
  text "PCB VIEWED FROM TOP SIDE" at -228.5,-655.67 h60
  text "BOARD #:" at 2248,-655.67 h60
  text ".PRJ_Number" at 2793.5,-655.67 h60
  text "REV:" at 3638,-655.67 h60
  text ".PCB_Rev" at 3929.5,-655.67 h60
  text "SVN REV:" at 4476,-655.67 h60
  text ".VersionControl_RevNumber" at 4982,-655.67 h60
  text "IGNORE ->" at -228.5,-858.49 h60
  text "PLOT NAME =" at -228.5,-1064.34 h60
  text ".plot_File_Name" at 577,-1064.34 h60
  text "GENERATED    :" at 2250,-1064.34 h60
  text ".Print_Date" at 3119.5,-1064.34 h60
  text ".Print_Time" at 3848.5,-1064.34 h60
  text "TEXAS INSTRUMENTS" at 5113,-1064.34 h60
M6 Assembly Bottom:
  lines w10: -292.5,-727.33 6309.5,-727.33 ; -290.5,-930.67 6309.5,-930.67 ; 1115.5,-1140.5 1115.5,-937.67 ; 1737.5,-727.33 1737.5,-524 ; 2577.5,-727.33 2577.5,-524 ; 3844.5,-1134 3844.5,-524 ; 4733.5,-1134 6309,-1134 6309,-524 -292.5,-524 -292.5,-1134 2304.5,-1134 6309.5,-1134 6309.5,-524
  text "COMPONENTS MARKED 'DNP' SHOULD NOT BE POPULATED." at 6102,-318 h60
  text ".VariantName" at 5058,-434 h60
  text "ASSEMBLY VARIANT:" at 6097,-434 h60
  text ".VersionControl_RevNumber" at 1035.5,-656.17 h60
  text "SVN REV:" at 1541.5,-656.17 h60
  text ".PCB_Rev" at 2088,-656.17 h60
  text "REV:" at 2379.5,-656.17 h60
  text ".PRJ_Number" at 3224,-656.17 h60
  text "BOARD #:" at 3769.5,-656.17 h60
  text "PCB VIEWED FROM BOTTOM SIDE" at 6246,-656.17 h60
  text "IGNORE ->" at 2547.85,-858.49 h60
  text "TEXAS INSTRUMENTS" at 904.5,-1064.84 h60
  text ".Print_Time" at 2169,-1064.84 h60
  text ".Print_Date" at 2898,-1064.84 h60
  text "GENERATED    :" at 3767.5,-1064.84 h60
  text ".plot_File_Name" at 5440.5,-1064.84 h60
  text "PLOT NAME =" at 6246,-1064.84 h60
M9 Title Sheet:
  drawing of 57 lines, arcs and shapes, not listed
  text "1" at 739.84,8036.5 h70
  text "2" at 3235.5,8036.5 h70
  text "3" at 5724.84,8036.5 h70
  text "4" at 8231.51,8036.5 h70
  text "5" at 10730.5,8036.5 h70
  text "6" at 13235.5,8036.5 h70
  text "A" at -416.5,6893.5 h70
  text "A" at 14383.5,6893.5 h70
  text "B" at -416.5,4513.5 h70
  text "B" at 14383.5,4513.5 h70
  text "C" at -416.5,2138.5 h70
  text "C" at 14383.5,2138.5 h70
  text "PROJECT TITLE:" at 11343.5,277.5 h45
  text ".PRJ_Title" at 11393.5,144.17 h70
  text "DESIGNED FOR:" at 11343.5,-23.5 h45
  text ".PRJ_Customer" at 11393.5,-163.5 h70
  text "D" at -416.5,-231.5 h70
  text "D" at 14383.5,-231.5 h70
  text "FILE NAME:" at 11343.5,-323.5 h45
  text ".PCB_File_Name_No_Path" at 11393.5,-443.5 h70
  text "Texas Instruments (TI) and/or its licensors do not warrant the accuracy or completeness of this specification" at 6374,-605.34 h45
  text "ENGINEER:" at 11343.5,-613.5 h45
  text "LAYOUT BY:" at 12848.5,-613.5 h45
  text "or any information contained therein. TI and/or its licensors do not warrant that this design will meet" at 6329.01,-718 h45
  text ".PRJ_Engineer" at 11393.5,-768.49 h70
  text ".PCB_Layout" at 12899,-768.49 h70
  text "the specifications, will be suitable for your application or fit for any particular purpose, or will operate in" at 6329.01,-830.67 h45
  text "ALTIUM DESIGNER VERSION:" at 12848.5,-923.5 h45
  text "an implementation. TI and/or its licensors do not warrant that the design is production worthy. You should" at 6329.01,-943.33 h45
  text "completely validate and test your design implementation to confirm the system functionality for your application." at 6374,-1056 h45
  text ".print_Scale" at 11393.5,-1056.83 h70
  text ".Application_BuildNumber" at 12899,-1056.83 h70
  text "1" at 739.84,-1263.5 h70
  text "2" at 3235.5,-1263.5 h70
  text "3" at 5724.84,-1263.5 h70
  text "4" at 8231.51,-1263.5 h70
  text "5" at 10730.5,-1263.5 h70
  text "6" at 13235.5,-1263.5 h70
M10 Fab Notes:
  drawing of 220 lines, arcs and shapes, not listed
  text "DESIGN INFORMATION" at 12381.02,6810 h60
  text "(REFER ALSO ARRAY/PANEL PROFILING INFORMATION)" at 12019.46,6648.29 h60
  text "BOARD SIZE" at 11333.46,6644 h60
  text "110mm" at 11795.78,6516.18 h60
  text "X" at 12301.46,6516.18 h60
  text "90mm" at 12532.78,6516.18 h60
  text "Number of Layers :" at 11736.46,6319 h60
  text "2" at 12831.27,6309 h60
  text "MIN. TRACK WIDTH:" at 11736.46,6180 h60
  text "15" at 12832.7,6180 h60
  text "MIL" at 12987.46,6180 h60
  text "MIN. CLEARANCE:" at 11736.46,6048 h60
  text "12" at 12832.7,6048 h60
  text "MIL" at 12987.46,6048 h60
  text "MIN. VIA PAD SIZE:" at 11736.46,5916 h60
  text "40" at 12802.71,5916 h60
  text "MIL" at 12987.46,5916 h60
  text "0.152mm (6MIL)" at 12431.46,5774.29 h60
  text "MINIMUM ANNULAR RING" at 11407.23,5770 h60
  text "EXTERNAL" at 13139.46,5770 h60
  text "PER" at 11607.23,5652 h60
  text "IPC-D-275 CLASS 2 LEVEL C" at 11827.23,5652 h60
  text "MIL, HOLES" at 13315.46,5539.71 h60
  text "+/-" at 12923,5539 h60
  text "+/-" at 13777,5539 h60
  text "REGISTRATION TOLERANCES:" at 11407.23,5534 h60
  text "METAL" at 12607,5534 h60
  text "5" at 13183.2,5534 h60
  text "3" at 14016.2,5534 h60
  text "MIL" at 14132.46,5534 h60
  text "MATERIAL:" at 11332.46,5324.54 h60
  text "FR-4 High Tg" at 12318.9,5184.21 h60
  text "X" at 11606.46,5175.64 h60
  text "FR-408" at 11753.46,5175.64 h60
  text "OTHER" at 13241.46,5175.64 h60
  text "62 MIL (1.6mm) +/-10%" at 12073.56,5012.92 h60
  text "THICKNESS:" at 11407.23,5008.64 h60
  text "X" at 11945.4,5008.64 h60
  text "OTHER" at 13358.46,5008.64 h60
  text "TOLERANCE:" at 11407.23,4850.64 h60
  text "X" at 12246.53,4850.64 h60
  text "ANSI IPC-6012 TYPE 3 CLASS 2" at 12433.48,4850.64 h60
  text "OTHER +/-" at 12433.46,4694.64 h60
  text "BOW & TWIST:" at 11407.23,4537.64 h60
  text "X" at 12246.53,4537.64 h60
  text "ANSI IPC-6012 TYPE 3 CLASS 2" at 12433.48,4537.64 h60
  text "OTHER +/-" at 12433.46,4379.13 h60
  text "COPPER THICKNESS (FINISHED):" at 11332.46,4243.64 h60
  text "1.4MIL (1oz)" at 12212.46,4090.92 h60
  text "2MIL (1.4oz)" at 12979.46,4090.92 h60
  text "2.8MIL (2oz)" at 13706.46,4090.92 h60
  text "OUTER:" at 11689.46,4086.64 h60
  text "X" at 12084,4086 h60
  text "1.4MIL (1oz)" at 12212.46,3933.92 h60
  text "2.8MIL (2oz)" at 12979.46,3933.92 h60
  text "N/A" at 13706,3934.29 h60
  text "INNER SIGNAL:" at 11400.38,3929.64 h60
  text "X" at 12085.42,3929.64 h60
  text "DRILLING:" at 11332.46,3790.64 h60
  text "REFERENCE:" at 11407.23,3673.64 h60
  text "X" at 12055.46,3673.64 h60
  text "AS SHOWN" at 12242.46,3673.64 h60
  text "X" at 12956.46,3673.64 h60
  text "NC_DRILL FILES" at 13093.46,3673.64 h60
  text "PTH MIN COPPER THICKNESS:" at 11407.23,3515.64 h60
  text "X" at 12757.46,3515.64 h60
  text "1MIL" at 12894.46,3515.64 h60
  text "OTHER" at 13391.46,3515.64 h60
  text "BOARD FINISH:" at 11332.46,3356.64 h60
  text "SILKSCREEN:" at 11487.68,3238.64 h60
  text "X" at 12436.46,3238.64 h60
  text "TOP" at 12562.46,3238.64 h60
  text "BOTTOM" at 13073.46,3238.64 h60
  text "SILKSCREEN COLOR:" at 11487.68,3071.64 h60
  text "X" at 12435.42,3071.64 h60
  text "WHITE" at 12562.46,3071.64 h60
  text "OTHER" at 13073.46,3071.64 h60
  text "SOLDER RESIST COLOR:" at 11487.68,2901.64 h60
  text "X" at 12055.42,2742.44 h60
  text "GREEN" at 12182.46,2742.44 h60
  text "BLUE" at 12773.46,2742.44 h60
  text "OTHER" at 13311.46,2742.44 h60
  text "IMMERSION GOLD (ENIG)" at 12393.46,2553.92 h60
  text "ENEPIG" at 13731,2550.64 h60
  text "SURFACE FINISH:" at 11332.46,2549.64 h60
  text "X" at 12206.51,2549.64 h60
  text "IMM. TIN/SILVER OR EQUIV" at 11662,2392.64 h60
  text "OTHER" at 13093.46,2392.64 h60
  text "ARRAY/PANEL:" at 11332.46,2213.64 h60
  text "CUT AND TRIM PER MECH LAYER 1" at 12393.46,2209.35 h60
  text "N.C. ROUTE" at 12393.46,2057.64 h60
  text "X" at 13072.46,2057.64 h60
  text "V. SCORE" at 13259.46,2057.64 h60
  text "CERTIFICATION:" at 11332.46,1920.64 h60
  text "MATERIALS AND WORKMANSHIP FOR ALL PCBS" at 12057.46,1920.64 h60
  text "TO MEET OR EXCEED THE REQUIREMENTS OF:" at 12057.46,1822.64 h60
  text "X" at 11683.96,1686.13 h60
  text "ANSI IPC-A-600F CLASS ->" at 11822.96,1686.13 h60
  text "X" at 13462.02,1686.13 h60
  text "2" at 13580.96,1686.14 h60
  text "1" at 13265.96,1684.64 h60
  text "3" at 13934.96,1684.64 h60
  text "X" at 11686.02,1526.64 h60
  text "UL 94V-0" at 11822.96,1526.64 h60
  text "X" at 12498.02,1526.64 h60
  text "RoHS" at 12634.96,1526.64 h60
  text "OTHER" at 13279.36,1526.64 h60
  text "PER ORDER" at 13676.42,1526.64 h60
  text "ADDITIONAL REQUIREMENTS:" at 11332.46,1385.64 h60
  text "VIA TENTING:" at 12807,1290 h60
  text "X" at 13595.29,1290.11 h60
  text "YES" at 13378.67,1280.92 h60
  text "NO" at 13773.47,1280.69 h60
  text "MICROSECTION:" at 11407.23,1270.64 h60
  text "YES" at 12312.96,1270.64 h60
  text "REQUIRED" at 13174.46,1114.49 h60
  text "BARE BOARD ELEC. TEST:" at 11407.23,1111.64 h60
  text "NONE" at 12712.96,1111.64 h60
  text "X" at 13047.46,1111.64 h60
  text "PER ORDER" at 13766.46,1111.64 h60
  text "MANUFACTURER'S UL:" at 11407.23,954.64 h60
  text "RAIL" at 12572.96,950.35 h60
  text "METAL" at 13064.77,950.35 h60
  text "X" at 13440,950 h60
  text "SILK" at 13576.46,950.35 h60
M11 Gerber Information:
  lines w10: -292,-930.17 6308,-930.17 ; -292,-726.83 6310,-726.83 ; -292,-523.5 -292,-1133.5 3713,-1133.5 6310,-1133.5 6310,-523.5 -291.5,-523.5 -291.5,-1133.5 1284,-1133.5 ; 2173,-1133.5 2173,-523.5 ; 3440,-726.83 3440,-523.5 ; 4280,-726.83 4280,-523.5 ; 4902,-1140 4902,-937.17
  text "ALL ARTWORK VIEWED FROM TOP SIDE" at -228.5,-655.67 h60
  text "BOARD #:" at 2248,-655.67 h60
  text ".PRJ_Number" at 2793.5,-655.67 h60
  text "REV:" at 3638,-655.67 h60
  text ".PCB_Rev" at 3929.5,-655.67 h60
  text "SVN REV:" at 4476,-655.67 h60
  text ".VersionControl_RevNumber" at 4982,-655.67 h60
  text "LAYER NAME =" at -228.5,-858.49 h60
  text "PLOT NAME =" at -228.5,-1064.34 h60
  text ".plot_File_Name" at 577,-1064.34 h60
  text "GENERATED    :" at 2250,-1064.34 h60
  text ".Print_Date" at 3119.5,-1064.34 h60
  text ".Print_Time" at 3848.5,-1064.34 h60
  text "TEXAS INSTRUMENTS" at 5113,-1064.34 h60
M12 Stackup:
  lines w6: 11360,7460 13910,7460 ; 11360,7564.4 13910,7564.4 ; 11300,6975 ccw(c11334,6975) 11334,6941 13936,6941 ccw(c13936,6975) 13970,6975 13970,7681 ccw(c13936,7681) 13936,7715 11334,7715 ccw(c11334,7681) 11300,7681 11300,6975
  text "Layer Stack Up Detail for: TIDA-00182" at 11360,7597.1 h57
  text "Layer" at 11360,7525.4 h24
  text "Gerber" at 12255.81,7525.4 h24
  text "Copper" at 12819.33,7525.4 h24
  text "Dielectric" at 13422.04,7525.4 h24
  text "Name" at 11360,7477.4 h24
  text "Document" at 12255.81,7477.4 h24
  text "Thickness" at 12819.33,7477.4 h24
  text "Material" at 13422.04,7477.4 h24
  text "Top Solder Mask" at 11360,7384.44 h34
  text "(.GTS)" at 12255.81,7384.44 h34
  text "Solder Resist" at 13422.04,7384.44 h34
  text "Top Layer" at 11360,7287.69 h34
  text "(.GTL)" at 12255.81,7287.69 h34
  text "1.4mil" at 12819.33,7287.69 h34
  text "FR-4" at 13422.04,7239.31 h34
  text "Bottom Layer" at 11360,7190.94 h34
  text "(.GBL)" at 12255.81,7190.94 h34
  text "1.4mil" at 12819.33,7190.94 h34
  text "Bottom Solder Mask" at 11360,7094.19 h34
  text "(.GBS)" at 12255.81,7094.19 h34
  text "Solder Resist" at 13422.04,7094.19 h34
M13 Component Bodies Top:
  text ".Layer_Name" at 577,-858.49 h60
M14 Component Bodies Bottom:
  text ".Layer_Name" at 577,-858.49 h60
M15 Courtyards Top:
  text ".Layer_Name" at 577,-858.49 h60
M16 Courtyards Bottom:
  text ".Layer_Name" at 577,-858.49 h60
Drill Drawing:
  text ".legend" at 5470,770 h60
  text "Drill Table" at 5480,600 h60
  text "DRILL TOLERANCE" at 5474.72,486.52 h60
  text "FOR PTH +/- 3MIL" at 5475.14,377.09 h60
  text ".Layer_Name" at 577,-858.49 h60

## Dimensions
0,0 to 0,3543.31 on Drill Drawing
4330.71,3543.31 to 0,3543.31 on Drill Drawing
